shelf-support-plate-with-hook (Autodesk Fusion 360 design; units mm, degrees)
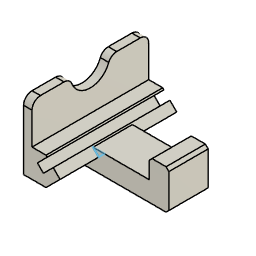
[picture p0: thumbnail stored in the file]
base_feature "Base Feature2"
base_feature "Base Feature1" bodies "Support Mount"
combine "Combine1"
extrude "Extrude1" add sketch "Reconstructed-Sketch1" blind -14
named bodies: "Support Mount"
